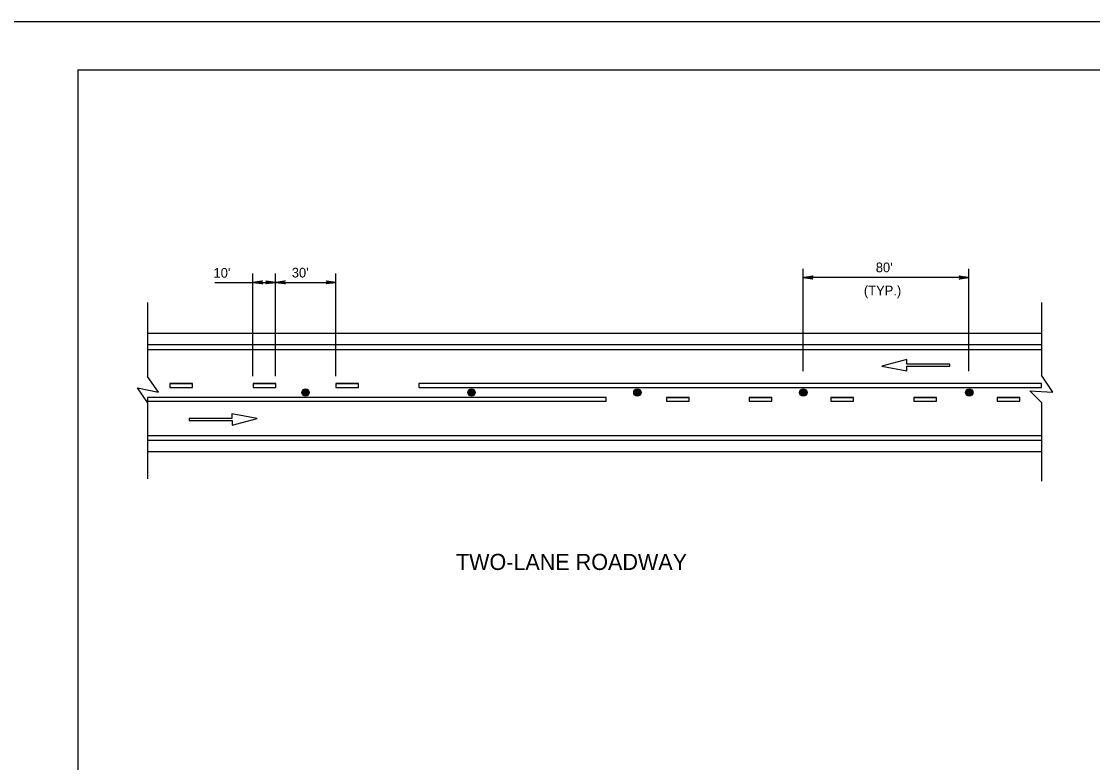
# Model space of a CAD drawing. Extents: x 639362 to 641108, y 298458 to 299646.
# Drawn here: x 640225.9 to 640558.2, y 299415.8 to 299645.6 of the extents above; entities that cross this region are included whole.
import ezdxf

# ---------------------------------------------------------------- set-up
doc = ezdxf.new("R2010")
doc.units = 0
for name, color, linetype in [('1', 7, 'Continuous'), ('2', 7, 'Continuous'), ('3', 7, 'Continuous'), ('PLT-BNDY', 7, 'Continuous')]:
    doc.layers.add(name, color=color, linetype=linetype)

# ---------------------------------------------------------------- blocks, each defined once
blk = doc.blocks.new('RARROW')
at = {"layer": '3'}
blk.add_lwpolyline([(-2.2695, 0.285), (-2.184875, 0.12075), (0, 0), (-2.2695, 0.285), (-2.38575, 0.384625), (0, 0), (-2.183125, -0.108), (-2.262875, -0.2705), (0, 0), (-2.38575, -0.379125), (-2.262875, -0.2705)], dxfattribs=at)

msp = doc.modelspace()

# ---------------------------------------------------------------- linework, layer by layer
at = {"layer": '1'}
for q in [(641029.31, 299630.63), (640243.31, 299066.63)]:
    msp.add_line((640243.31, 299630.63), q, dxfattribs=at)
at = {"layer": '2'}
for p, q in [((640468.44, 299537.15), (640468.44, 299568.92)), ((640519.83, 299537.15), (640519.83, 299568.92)), ((640285.82, 299564.71), (640304.65, 299564.71)), ((640297.63, 299535.66), (640297.63, 299567.43)), ((640304.65, 299535.66), (640304.65, 299567.43)), ((640304.65, 299564.71), (640323.37, 299564.71)), ((640323.37, 299535.66), (640323.37, 299567.43)), ((640519.83, 299566.2), (640468.44, 299566.2)), ((640264.93, 299558.51), (640264.93, 299535.55)), ((640542.37, 299558.51), (640542.37, 299535.95)), ((640264.93, 299548.92), (640542.37, 299548.92)), ((640264.93, 299545.42), (640542.37, 299545.42)), ((640264.93, 299543.92), (640542.37, 299543.92)), ((640500.53, 299540.83), (640492.81, 299538.71)), ((640492.81, 299538.71), (640500.61, 299537.24)), ((640500.53, 299539.38), (640500.53, 299540.83)), ((640513.86, 299539.38), (640500.53, 299539.38)), ((640500.61, 299537.24), (640500.61, 299538.68)), ((640500.61, 299538.68), (640513.86, 299538.68)), ((640513.86, 299538.68), (640513.86, 299539.38)), ((640268.42, 299530.66), (640264.93, 299535.55)), ((640545.86, 299530.66), (640542.37, 299535.95)), ((640264.93, 299527.43), (640261.88, 299532.01)), ((640261.88, 299532.01), (640268.42, 299530.66)), ((640278.91, 299533.35), (640271.89, 299533.35)), ((640271.89, 299533.35), (640278.91, 299533.33)), ((640278.91, 299532.13), (640278.91, 299533.35)), ((640304.76, 299533.35), (640297.74, 299533.35)), ((640297.74, 299533.35), (640304.76, 299533.33)), ((640304.76, 299532.13), (640304.76, 299533.35)), ((640330.42, 299533.35), (640323.41, 299533.35)), ((640323.41, 299533.35), (640330.42, 299533.33)), ((640330.42, 299532.13), (640330.42, 299533.35)), ((640542.37, 299533.33), (640349.14, 299533.33)), ((640349.14, 299533.33), (640349.14, 299532.13)), ((640349.14, 299532.13), (640542.37, 299532.13)), ((640542.37, 299532.13), (640542.37, 299533.33)), ((640407.24, 299529.02), (640264.97, 299529.02)), ((640264.97, 299529.02), (640264.97, 299527.82)), ((640407.24, 299527.82), (640407.24, 299529.02)), ((640433, 299529.04), (640425.98, 299529.04)), ((640425.98, 299529.04), (640433, 299529.02)), ((640433, 299527.82), (640433, 299529.04)), ((640458.68, 299529.04), (640451.66, 299529.04)), ((640451.66, 299529.04), (640458.68, 299529.02)), ((640458.68, 299527.82), (640458.68, 299529.04)), ((640484, 299529.04), (640476.98, 299529.04)), ((640476.98, 299529.04), (640484, 299529.02)), ((640484, 299527.82), (640484, 299529.04)), ((640509.8, 299529.04), (640502.78, 299529.04)), ((640502.78, 299529.04), (640509.8, 299529.02)), ((640509.8, 299527.82), (640509.8, 299529.04)), ((640535.59, 299529.04), (640528.57, 299529.04)), ((640528.57, 299529.04), (640535.59, 299529.02)), ((640535.59, 299527.82), (640535.59, 299529.04)), ((640542.37, 299527.43), (640538.76, 299531.05)), ((640538.76, 299531.05), (640545.86, 299530.66)), ((640264.93, 299527.43), (640264.93, 299503.78)), ((640264.97, 299527.82), (640407.24, 299527.82)), ((640542.37, 299527.43), (640542.37, 299503.03)), ((640291.19, 299522.54), (640277.95, 299522.54)), ((640277.95, 299522.54), (640277.95, 299521.84)), ((640277.95, 299521.84), (640291.27, 299521.84)), ((640299, 299522.51), (640291.19, 299523.98)), ((640291.19, 299523.98), (640291.19, 299522.54)), ((640291.27, 299520.39), (640299, 299522.51)), ((640291.27, 299521.84), (640291.27, 299520.39)), ((640264.93, 299517.23), (640542.37, 299517.23)), ((640264.93, 299515.73), (640542.37, 299515.73)), ((640264.93, 299512.23), (640542.37, 299512.23))]:
    msp.add_line(p, q, dxfattribs=at)
for points in [[(640278.91, 299533.33), (640271.89, 299533.33), (640271.89, 299532.13), (640278.91, 299532.13)], [(640304.76, 299533.33), (640297.74, 299533.33), (640297.74, 299532.13), (640304.76, 299532.13)], [(640330.42, 299533.33), (640323.41, 299533.33), (640323.41, 299532.13), (640330.42, 299532.13)], [(640433, 299529.02), (640425.98, 299529.02), (640425.98, 299527.82), (640433, 299527.82)], [(640458.68, 299529.02), (640451.66, 299529.02), (640451.66, 299527.82), (640458.68, 299527.82)], [(640484, 299529.02), (640476.98, 299529.02), (640476.98, 299527.82), (640484, 299527.82)], [(640509.8, 299529.02), (640502.78, 299529.02), (640502.78, 299527.82), (640509.8, 299527.82)], [(640535.59, 299529.02), (640528.57, 299529.02), (640528.57, 299527.82), (640535.59, 299527.82)]]:
    msp.add_lwpolyline(points, dxfattribs=at)
for centre, radius in [((640314, 299530.57), 1.15), ((640314, 299530.57), 1.07), ((640314, 299530.57), 0.985), ((640314, 299530.57), 0.904), ((640314, 299530.57), 0.822), ((640365.49, 299530.57), 1.15), ((640365.49, 299530.57), 1.07), ((640365.49, 299530.57), 0.985), ((640365.49, 299530.57), 0.904), ((640365.49, 299530.57), 0.822), ((640416.97, 299530.57), 1.15), ((640416.97, 299530.57), 1.07), ((640416.97, 299530.57), 0.985), ((640416.97, 299530.57), 0.904), ((640416.97, 299530.57), 0.822), ((640468.45, 299530.57), 1.15), ((640468.45, 299530.57), 1.07), ((640468.45, 299530.57), 0.985), ((640468.45, 299530.57), 0.904), ((640468.45, 299530.57), 0.822), ((640519.94, 299530.57), 1.15), ((640519.94, 299530.57), 1.07), ((640519.94, 299530.57), 0.985), ((640519.94, 299530.57), 0.904), ((640519.94, 299530.57), 0.822), ((640314, 299530.57), 0.741), ((640314, 299530.57), 0.659), ((640314, 299530.57), 0.578), ((640314, 299530.57), 0.496), ((640314, 299530.57), 0.414), ((640314, 299530.57), 0.333), ((640314, 299530.57), 0.251), ((640314, 299530.57), 0.17), ((640314, 299530.57), 0.0881), ((640365.49, 299530.57), 0.741), ((640365.49, 299530.57), 0.659), ((640365.49, 299530.57), 0.578), ((640365.49, 299530.57), 0.496), ((640365.49, 299530.57), 0.414), ((640365.49, 299530.57), 0.333), ((640365.49, 299530.57), 0.251), ((640365.49, 299530.57), 0.17), ((640365.49, 299530.57), 0.0881), ((640416.97, 299530.57), 0.741), ((640416.97, 299530.57), 0.659), ((640416.97, 299530.57), 0.578), ((640416.97, 299530.57), 0.496), ((640416.97, 299530.57), 0.414), ((640416.97, 299530.57), 0.333), ((640416.97, 299530.57), 0.251), ((640416.97, 299530.57), 0.17), ((640416.97, 299530.57), 0.0881), ((640468.45, 299530.57), 0.741), ((640468.45, 299530.57), 0.659), ((640468.45, 299530.57), 0.578), ((640468.45, 299530.57), 0.496), ((640468.45, 299530.57), 0.414), ((640468.45, 299530.57), 0.333), ((640468.45, 299530.57), 0.251), ((640468.45, 299530.57), 0.17), ((640468.45, 299530.57), 0.0881), ((640519.94, 299530.57), 0.741), ((640519.94, 299530.57), 0.659), ((640519.94, 299530.57), 0.578), ((640519.94, 299530.57), 0.496), ((640519.94, 299530.57), 0.414), ((640519.94, 299530.57), 0.333), ((640519.94, 299530.57), 0.251), ((640519.94, 299530.57), 0.17), ((640519.94, 299530.57), 0.0881)]:
    msp.add_circle(centre, radius, dxfattribs=at)
at = {"layer": 'PLT-BNDY'}
msp.add_lwpolyline([(640203.31, 299645.63), (641044.31, 299645.63), (641044.31, 299051.63), (640203.31, 299051.63)], close=True, dxfattribs=at)

# ---------------------------------------------------------------- block references
at = {"layer": '2', "xscale": 1.2574347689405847, "yscale": 1.3092961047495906, "rotation": 180}
for p in [(640297.63, 299564.71), (640304.65, 299564.71), (640468.44, 299566.2)]:
    msp.add_blockref('RARROW', p, dxfattribs=at)
at = {"layer": '2', "xscale": 1.2574347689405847, "yscale": 1.3092961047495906}
for p in [(640304.65, 299564.71), (640323.37, 299564.71), (640519.83, 299566.2)]:
    msp.add_blockref('RARROW', p, dxfattribs=at)

# ---------------------------------------------------------------- texts
at = {"layer": '2'}
for s, height, p in [(" 10'", 3, (640284.34, 299566.16)), (" 30'", 3, (640308.62, 299566.23)), ("80'", 3, (640490.93, 299567.85)), ('(TYP.)', 3, (640487.24, 299560.68)), ('TWO-LANE ROADWAY', 5, (640360.68, 299475.52))]:
    msp.add_text(s, height=height, dxfattribs=at).set_placement(p)

doc.saveas('drawing.dxf')
